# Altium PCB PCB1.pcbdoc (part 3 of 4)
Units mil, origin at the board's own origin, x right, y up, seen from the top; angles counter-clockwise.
Board outline 4701.34 x 4268.46 mil, 2 copper layers (Top Layer, Bottom Layer); 341 components, 58 nets, 1384 pads, 312 vias.
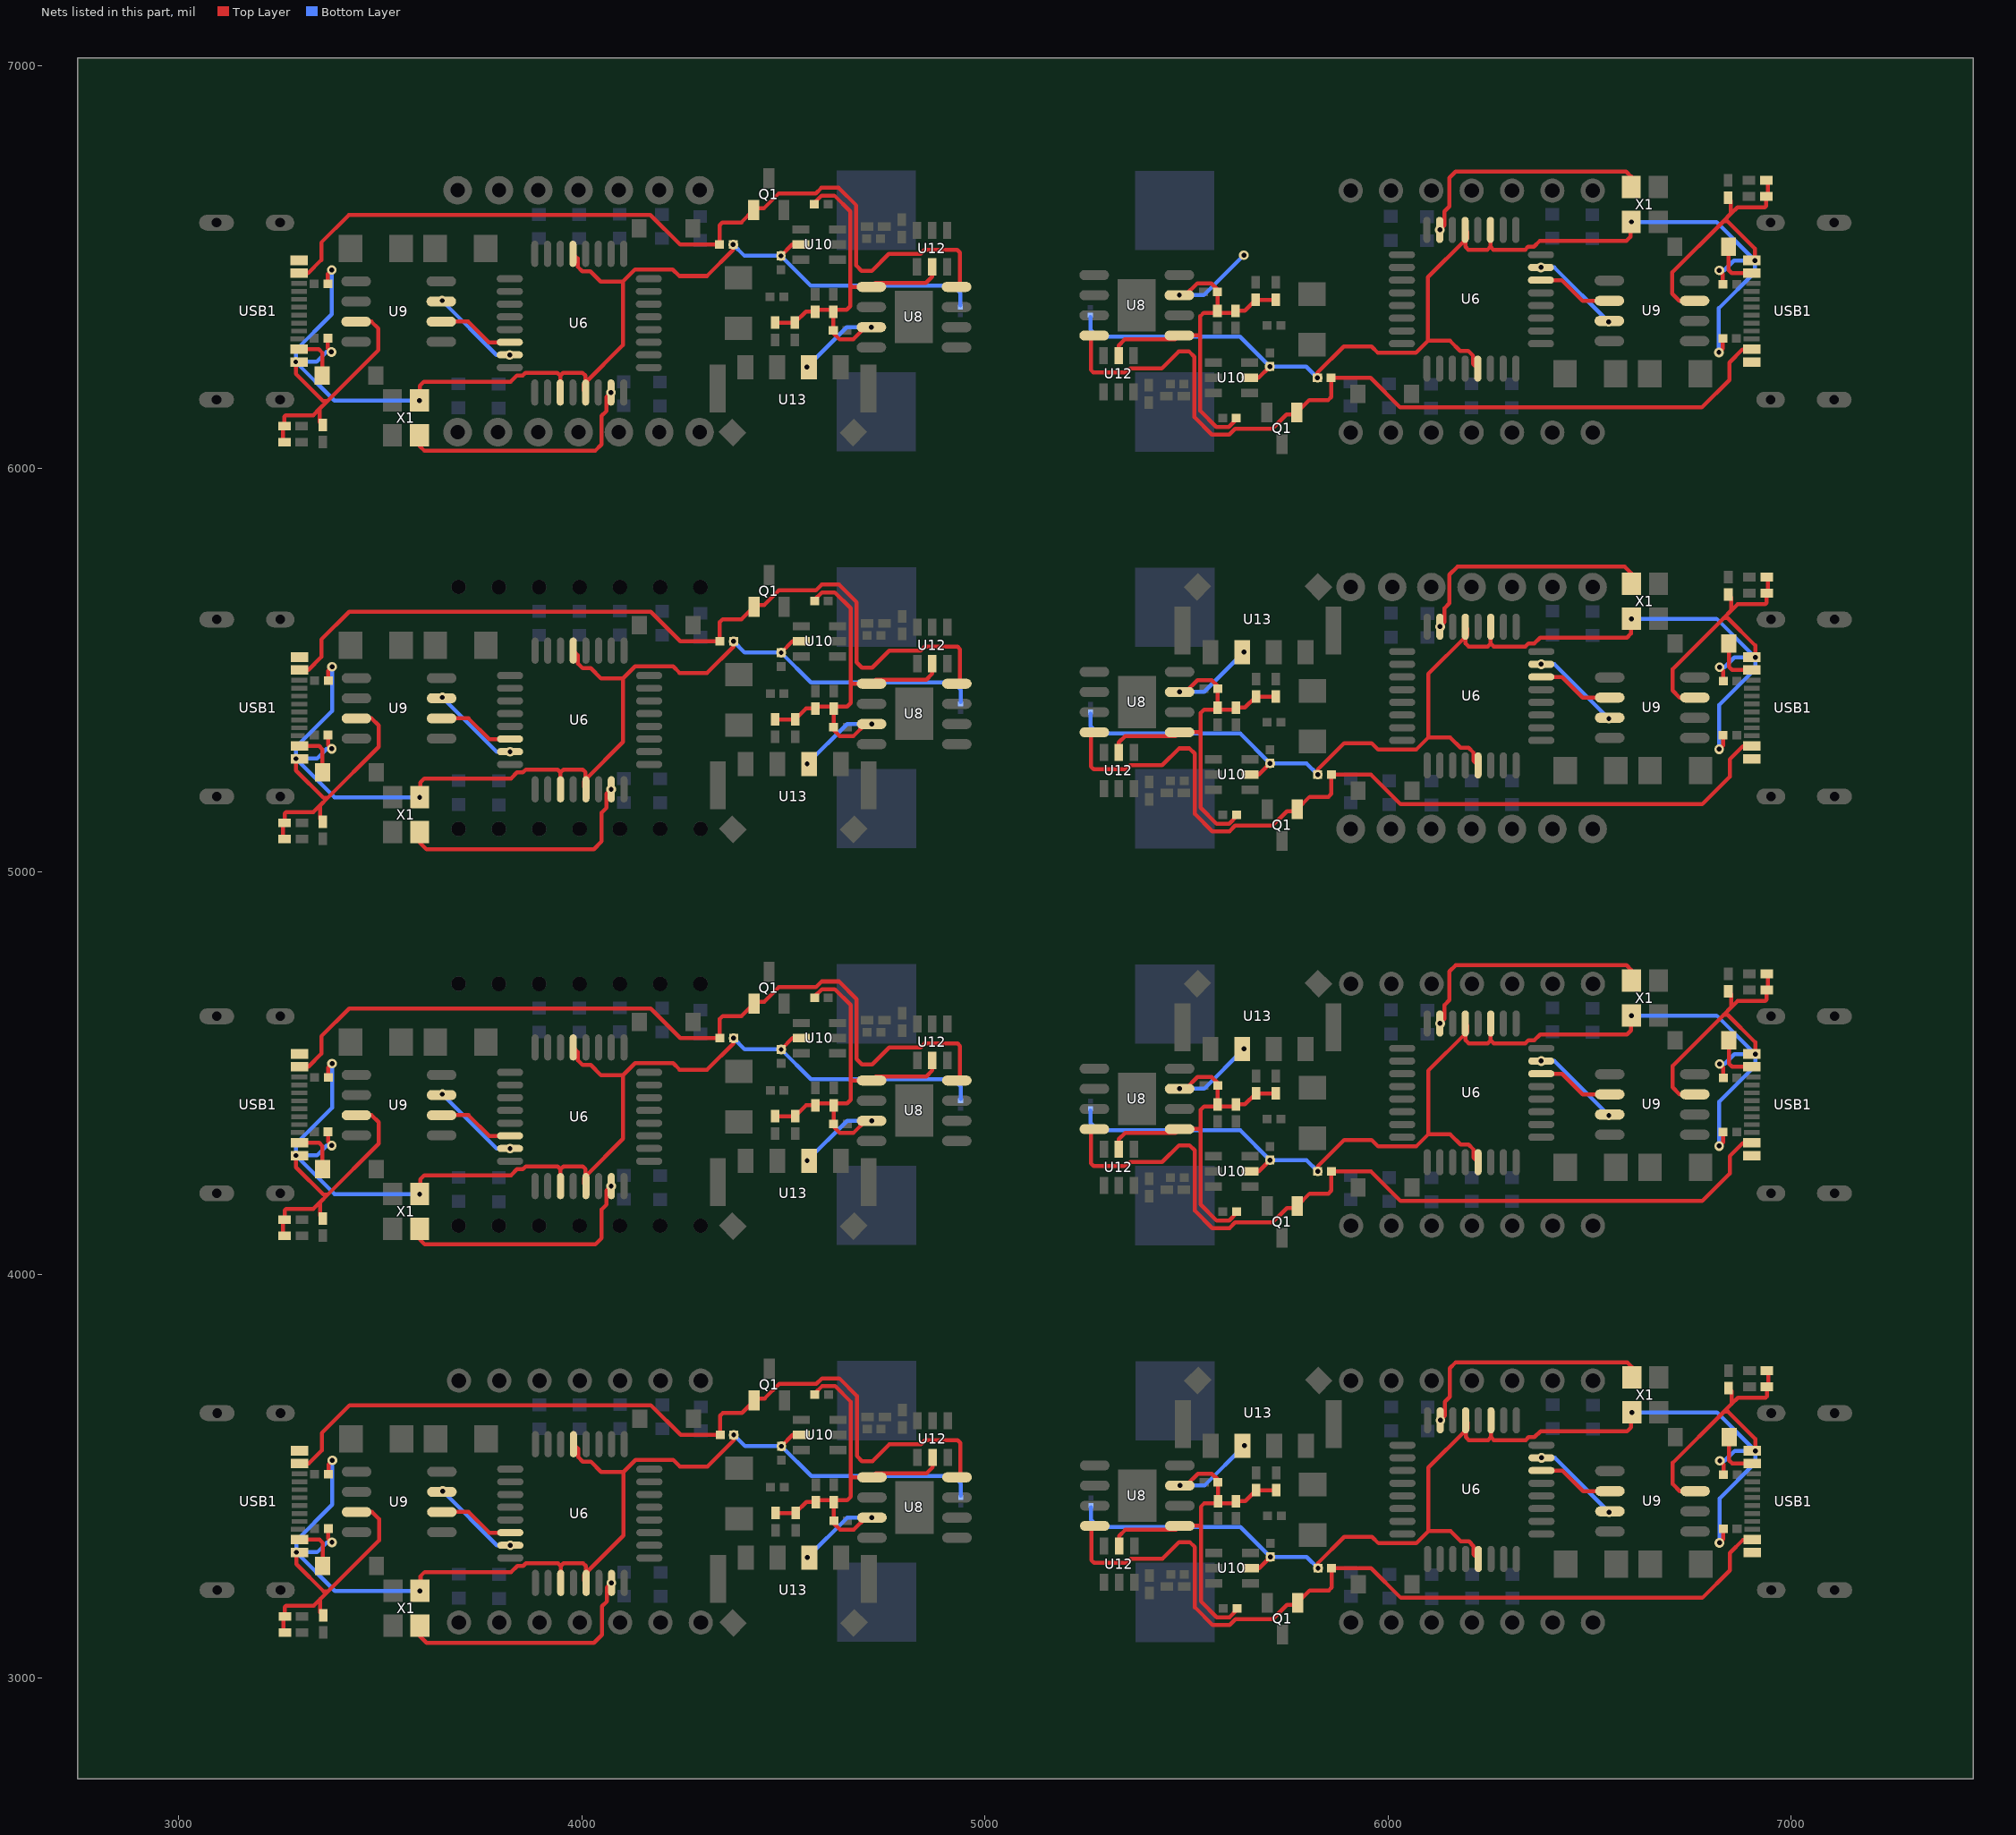
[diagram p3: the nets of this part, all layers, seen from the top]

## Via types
v1: diameter 24.02, hole 12.01, Top Layer to Bottom Layer, 312 vias

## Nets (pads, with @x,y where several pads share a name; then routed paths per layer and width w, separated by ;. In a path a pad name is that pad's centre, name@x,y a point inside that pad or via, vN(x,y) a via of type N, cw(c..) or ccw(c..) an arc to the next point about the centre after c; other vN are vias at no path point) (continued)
POWER_GND: C15.2 C16.2 C19.1 C20.1 C21.2 C25.1 C27.1 R22.2 R48.2 R49.2 R50.2 R51.1 R52.1 R54.1 U6.3 U6.5 U6.21 U8.1 U8.3 U9.3 U10.2 U12.2 U13.2 USB1.A1B12 USB1.B1A12 X1.2 | length 37515.7
  Top Layer w10: C21.2@3262.65,6065.59 3259.11,6069.13 3259.11,6102.05 C25.1@3262.65,6105.59 3262.65,6129.1 3266.01,6132.46 3334.38,6132.46 3350.46,6148.55 ; C21.2@3263.32,4097.09 3259.78,4100.63 3259.78,4133.55 C25.1@3263.32,4137.09 3263.32,4160.6 3266.68,4163.96 3335.04,4163.96 3351.13,4180.05 ; C21.2@3263.32,5081.34 3259.78,5084.88 3259.78,5117.8 C25.1@3263.32,5121.34 3263.32,5144.85 3266.68,5148.21 3335.04,5148.21 3351.13,5164.3 ; C21.2@3263.99,3112.83 3260.45,3116.37 3260.45,3149.29 C25.1@3263.99,3152.83 3263.99,3176.35 3267.35,3179.71 3335.71,3179.71 3351.8,3195.79 ; v1(3290.88,6264.61) 3290.88,6235.32 3359.26,6166.94 3368.85,6166.94 ; v1(3291.55,4296.11) 3291.55,4266.81 3359.93,4198.43 3369.52,4198.43 ; v1(3291.55,5280.36) 3291.55,5251.06 3359.93,5182.68 3369.52,5182.68 ; v1(3292.22,3311.85) 3292.22,3282.56 3360.6,3214.18 3370.19,3214.18 ; C27.1@3357.65,6108.51 3350.46,6115.7 3350.46,6148.55 ; C27.1@3358.32,4140.01 3351.13,4147.19 3351.13,4180.05 ; C27.1@3358.32,5124.26 3351.13,5131.45 3351.13,5164.3 ; C27.1@3358.99,3155.75 3351.8,3162.94 3351.8,3195.79 ; R52.1@3370.31,6323.41 3370.31,6298.35 v1(3379.41,6289.25) ; R51.1@3370.71,6458.2 3370.71,6483.1 v1(3380.26,6492.65) ; R52.1@3370.98,4354.9 3370.98,4329.85 v1(3380.08,4320.75) ; R52.1@3370.98,5339.16 3370.98,5314.1 v1(3380.08,5305) ; R51.1@3371.38,4489.69 3371.38,4514.59 v1(3380.93,4524.14) ; R51.1@3371.38,5473.94 3371.38,5498.85 v1(3380.93,5508.39) ; R52.1@3371.64,3370.65 3371.64,3345.6 v1(3380.75,3336.49) ; R51.1@3372.05,3505.44 3372.05,3530.34 v1(3381.59,3539.89) ; U9.3@3440.67,6364.53 3478.49,6364.53 3495.98,6347.03 3495.98,6294.07 3368.85,6166.94 ; U9.3@3441.33,4396.02 3479.15,4396.02 3496.65,4378.52 3496.65,4325.57 3369.52,4198.43 ; U9.3@3441.33,5380.28 3479.15,5380.28 3496.65,5362.78 3496.65,5309.82 3369.52,5182.68 ; U9.3@3442,3411.77 3479.82,3411.77 3497.32,3394.27 3497.32,3341.31 3370.19,3214.18 ; X1.2@3599.11,6170.44 3599.11,6205.59 3609.11,6215.59 3824.11,6215.59 3839.03,6230.51 3853.45,6230.51 3860.6,6237.66 3939.8,6237.66 3946.87,6230.59 ; X1.2@3599.78,4201.93 3599.78,4237.09 3609.78,4247.09 3824.78,4247.09 3839.7,4262.01 3854.12,4262.01 3861.27,4269.16 3940.46,4269.16 3947.53,4262.09 ; X1.2@3599.78,5186.18 3599.78,5221.34 3609.78,5231.34 3824.78,5231.34 3839.7,5246.26 3854.12,5246.26 3861.27,5253.41 3940.46,5253.41 3947.53,5246.34 ; X1.2@3600.45,3217.68 3600.45,3252.83 3610.45,3262.83 3825.45,3262.83 3840.37,3277.75 3854.79,3277.75 3861.94,3284.9 3941.13,3284.9 3948.2,3277.83 ; U6.3@3946.87,6188.59 3946.87,6230.59 ; U6.3@3947.53,4220.09 3947.53,4262.09 ; U6.3@3947.53,5204.34 3947.53,5246.34 ; U6.3@3948.2,3235.83 3948.2,3277.83 ; U6.21@3978.36,6532.59 3990.02,6520.94 3990.02,6500.75 4001.64,6489.13 4021.83,6489.13 4047.12,6463.83 4102.1,6463.83 ; U6.21@3979.03,4564.09 3990.68,4552.43 3990.68,4532.24 4002.31,4520.62 4022.5,4520.62 4047.79,4495.33 4102.77,4495.33 ; U6.21@3979.03,5548.34 3990.68,5536.69 3990.68,5516.5 4002.31,5504.87 4022.5,5504.87 4047.79,5479.58 4102.77,5479.58 ; U6.21@3979.7,3579.83 3991.35,3568.18 3991.35,3547.99 4002.98,3536.37 4023.16,3536.37 4048.45,3511.08 4103.44,3511.08 ; U6.5@4009.86,6188.59 U6.5@4009.11,6189.34 ; U6.5@4010.53,4220.09 U6.5@4009.78,4220.83 ; U6.5@4010.53,5204.34 U6.5@4009.78,5205.09 ; U6.5@4011.19,3235.83 U6.5@4010.45,3236.58 ; v1(4375.86,6555.59) 4375.86,6542.85 4310.61,6477.6 4242.1,6477.6 4225.88,6493.82 4132.09,6493.82 4102.1,6463.83 ; v1(4376.52,4587.09) 4376.52,4574.34 4311.27,4509.09 4242.77,4509.09 4226.55,4525.31 4132.75,4525.31 4102.77,4495.33 ; v1(4376.52,5571.34) 4376.52,5558.6 4311.27,5493.35 4242.77,5493.35 4226.55,5509.57 4132.75,5509.57 4102.77,5479.58 ; v1(4377.19,3602.83) 4377.19,3590.09 4311.94,3524.84 4243.44,3524.84 4227.22,3541.06 4133.42,3541.06 4103.44,3511.08 ; C19.1@4479.57,6362.05 C20.1@4529.11,6362.05 4556.19,6389.13 C15.2@4579.11,6389.13 4584.11,6394.13 C16.2@4627.65,6394.13 ; C19.1@4480.24,4393.55 C20.1@4529.78,4393.55 4556.86,4420.63 C15.2@4579.78,4420.63 4584.78,4425.63 C16.2@4628.32,4425.63 ; C19.1@4480.24,5377.8 C20.1@4529.78,5377.8 4556.86,5404.88 C15.2@4579.78,5404.88 4584.78,5409.88 C16.2@4628.32,5409.88 ; C19.1@4480.91,3409.29 C20.1@4530.45,3409.29 4557.53,3436.37 C15.2@4580.45,3436.37 4585.45,3441.37 C16.2@4628.99,3441.37 ; v1(4494.11,6527.63) 4522.07,6555.59 U10.2@4543.87,6555.59 ; v1(4494.78,4559.13) 4522.73,4587.08 U10.2@4544.54,4587.08 ; v1(4494.78,5543.38) 4522.73,5571.33 U10.2@4544.54,5571.33 ; v1(4495.45,3574.87) 4523.4,3602.83 U10.2@4545.21,3602.83 ; R50.2@4577.07,6655.59 4577.07,6658.81 4595.47,6677.2 4626.83,6677.2 4666.44,6637.6 4666.44,6455.07 ; R50.2@4577.74,4687.09 4577.74,4690.31 4596.13,4708.7 4627.5,4708.7 4667.11,4669.1 4667.11,4486.57 ; R50.2@4577.74,5671.34 4577.74,5674.56 4596.13,5692.95 4627.5,5692.95 4667.11,5653.35 4667.11,5470.82 ; R50.2@4578.41,3702.83 4578.41,3706.05 4596.8,3724.45 4628.17,3724.45 4667.78,3684.84 4667.78,3502.31 ; v1(4718.5,6350.59) 4703.45,6350.59 4673.88,6321.02 4639.11,6321.02 4624.11,6336.02 4624.11,6390.59 C16.2@4627.65,6394.13 ; v1(4719.17,4382.09) 4704.12,4382.09 4674.54,4352.51 4639.78,4352.51 4624.78,4367.51 4624.78,4422.09 C16.2@4628.32,4425.63 ; v1(4719.17,5366.34) 4704.12,5366.34 4674.54,5336.76 4639.78,5336.76 4624.78,5351.76 4624.78,5406.34 C16.2@4628.32,5409.88 ; v1(4719.84,3397.83) 4704.79,3397.83 4675.21,3368.26 4640.45,3368.26 4625.45,3383.26 4625.45,3437.83 C16.2@4628.99,3441.37 ; U12.2@4864.11,6495.59 U12.2@4868.99,6500.47 ; U12.2@4864.78,4527.09 U12.2@4869.66,4531.97 ; U12.2@4864.78,5511.34 U12.2@4869.66,5516.22 ; U12.2@4865.45,3542.83 U12.2@4870.33,3547.71 ; U12.2@4869.11,6500.35 4869.11,6475.59 4854.11,6460.59 4728.5,6460.59 U8.1@4718.5,6450.59 4670.92,6450.59 4666.44,6455.07 ; U12.2@4869.78,4531.85 4869.78,4507.09 4854.78,4492.09 4729.17,4492.09 U8.1@4719.17,4482.09 4671.59,4482.09 4667.11,4486.57 ; U12.2@4869.78,5516.1 4869.78,5491.34 4854.78,5476.34 4729.17,5476.34 U8.1@4719.17,5466.34 4671.59,5466.34 4667.11,5470.82 ; U12.2@4870.45,3547.59 4870.45,3522.83 4855.45,3507.83 4729.84,3507.83 U8.1@4719.84,3497.83 4672.26,3497.83 4667.78,3502.31 ; U12.2@5331.72,6280.32 5331.72,6305.08 5346.72,6320.08 5472.33,6320.08 U8.1@5482.33,6330.08 5529.91,6330.08 5534.39,6325.6 ; U12.2@5331.84,6280.2 U12.2@5336.72,6285.08 ; U12.2@5332.38,4311.82 5332.38,4336.58 5347.38,4351.58 5472.99,4351.58 U8.1@5482.99,4361.58 5530.57,4361.58 5535.05,4357.1 ; U12.2@5332.38,5296.07 5332.38,5320.83 5347.38,5335.83 5472.99,5335.83 U8.1@5482.99,5345.83 5530.57,5345.83 5535.05,5341.35 ; U12.2@5332.5,4311.7 U12.2@5337.38,4316.58 ; U12.2@5332.5,5295.95 U12.2@5337.38,5300.83 ; U12.2@5333.05,3327.57 5333.05,3352.33 5348.05,3367.33 5473.66,3367.33 U8.1@5483.66,3377.33 5531.24,3377.33 5535.72,3372.85 ; U12.2@5333.17,3327.45 U12.2@5338.05,3332.33 ; v1(5482.33,6430.08) 5497.38,6430.08 5526.95,6459.66 5561.72,6459.66 5576.72,6444.66 5576.72,6390.08 C16.2@5573.18,6386.54 ; v1(5482.99,4461.58) 5498.04,4461.58 5527.62,4491.15 5562.38,4491.15 5577.38,4476.15 5577.38,4421.58 C16.2@5573.84,4418.04 ; v1(5482.99,5445.83) 5498.04,5445.83 5527.62,5475.4 5562.38,5475.4 5577.38,5460.4 5577.38,5405.83 C16.2@5573.84,5402.29 ; v1(5483.66,3477.33) 5498.71,3477.33 5528.29,3506.9 5563.05,3506.9 5578.05,3491.9 5578.05,3437.33 C16.2@5574.51,3433.79 ; R50.2@5623.76,6125.08 5623.76,6121.86 5605.36,6103.47 5573.99,6103.47 5534.39,6143.07 5534.39,6325.6 ; R50.2@5624.42,4156.58 5624.42,4153.36 5606.03,4134.96 5574.66,4134.96 5535.05,4174.57 5535.05,4357.1 ; R50.2@5624.42,5140.83 5624.42,5137.61 5606.03,5119.22 5574.66,5119.22 5535.05,5158.82 5535.05,5341.35 ; R50.2@5625.09,3172.33 5625.09,3169.11 5606.7,3150.71 5575.33,3150.71 5535.72,3190.31 5535.72,3372.85 ; U10.2@5656.95,6225.09 5678.76,6225.09 v1(5706.72,6253.04) ; U10.2@5657.62,4256.58 5679.43,4256.58 v1(5707.38,4284.54) ; U10.2@5657.62,5240.83 5679.43,5240.83 v1(5707.38,5268.79) ; U10.2@5658.29,3272.33 5680.1,3272.33 v1(5708.05,3300.29) ; C19.1@5721.26,6418.62 C20.1@5671.72,6418.62 5644.64,6391.54 C15.2@5621.72,6391.54 5616.72,6386.54 C16.2@5573.18,6386.54 ; C19.1@5721.92,4450.12 C20.1@5672.38,4450.12 5645.3,4423.04 C15.2@5622.38,4423.04 5617.38,4418.04 C16.2@5573.84,4418.04 ; C19.1@5721.92,5434.37 C20.1@5672.38,5434.37 5645.3,5407.29 C15.2@5622.38,5407.29 5617.38,5402.29 C16.2@5573.84,5402.29 ; C19.1@5722.59,3465.87 C20.1@5673.05,3465.87 5645.97,3438.79 C15.2@5623.05,3438.79 5618.05,3433.79 C16.2@5574.51,3433.79 ; v1(5824.97,6225.08) 5824.97,6237.83 5890.22,6303.07 5958.72,6303.07 5974.94,6286.85 6068.74,6286.85 6098.72,6316.84 ; v1(5825.64,4256.58) 5825.64,4269.32 5890.89,4334.57 5959.39,4334.57 5975.61,4318.35 6069.41,4318.35 6099.39,4348.33 ; v1(5825.64,5240.83) 5825.64,5253.57 5890.89,5318.82 5959.39,5318.82 5975.61,5302.6 6069.41,5302.6 6099.39,5332.59 ; v1(5826.31,3272.33) 5826.31,3285.07 5891.56,3350.32 5960.06,3350.32 5976.28,3334.1 6070.08,3334.1 6100.06,3364.08 ; U6.5@6190.97,6592.08 U6.5@6191.72,6591.33 ; U6.5@6191.64,4623.58 U6.5@6192.38,4622.83 ; U6.5@6191.64,5607.83 U6.5@6192.38,5607.08 ; U6.5@6192.3,3639.33 U6.5@6193.05,3638.58 ; U6.21@6222.46,6248.08 6210.81,6259.74 6210.81,6279.92 6199.19,6291.55 6179,6291.55 6153.71,6316.84 6098.72,6316.84 ; U6.21@6223.13,4279.58 6211.48,4291.23 6211.48,4311.42 6199.85,4323.04 6179.67,4323.04 6154.38,4348.33 6099.39,4348.33 ; U6.21@6223.13,5263.83 6211.48,5275.48 6211.48,5295.67 6199.85,5307.29 6179.67,5307.29 6154.38,5332.59 6099.39,5332.59 ; U6.21@6223.8,3295.33 6212.15,3306.98 6212.15,3327.17 6200.52,3338.79 6180.34,3338.79 6155.04,3364.08 6100.06,3364.08 ; U6.3@6253.96,6592.08 6253.96,6550.08 ; U6.3@6254.63,4623.58 6254.63,4581.58 ; U6.3@6254.63,5607.83 6254.63,5565.83 ; U6.3@6255.3,3639.33 6255.3,3597.33 ; X1.2@6601.72,6610.24 6601.72,6575.08 6591.72,6565.08 6376.72,6565.08 6361.79,6550.16 6347.37,6550.16 6340.22,6543.01 6261.03,6543.01 6253.96,6550.08 ; X1.2@6602.38,4641.73 6602.38,4606.58 6592.38,4596.58 6377.38,4596.58 6362.46,4581.66 6348.04,4581.66 6340.89,4574.51 6261.7,4574.51 6254.63,4581.58 ; X1.2@6602.38,5625.98 6602.38,5590.83 6592.38,5580.83 6377.38,5580.83 6362.46,5565.91 6348.04,5565.91 6340.89,5558.76 6261.7,5558.76 6254.63,5565.83 ; X1.2@6603.05,3657.48 6603.05,3622.33 6593.05,3612.33 6378.05,3612.33 6363.13,3597.4 6348.71,3597.4 6341.56,3590.25 6262.37,3590.25 6255.3,3597.33 ; U9.3@6760.16,6416.15 6722.34,6416.15 6704.84,6433.64 6704.84,6486.6 6831.98,6613.74 ; U9.3@6760.83,4447.64 6723.01,4447.64 6705.51,4465.14 6705.51,4518.1 6832.64,4645.23 ; U9.3@6760.83,5431.89 6723.01,5431.89 6705.51,5449.39 6705.51,5502.35 6832.64,5629.48 ; U9.3@6761.5,3463.39 6723.68,3463.39 6706.18,3480.89 6706.18,3533.84 6833.31,3660.98 ; v1(6820.57,6288.03) 6830.12,6297.57 R51.1@6830.12,6322.48 ; v1(6821.24,4319.52) 6830.78,4329.07 R51.1@6830.78,4353.97 ; v1(6821.24,5303.78) 6830.78,5313.32 R51.1@6830.78,5338.22 ; v1(6821.42,6491.42) 6830.52,6482.32 R52.1@6830.52,6457.27 ; v1(6821.91,3335.27) 6831.45,3344.82 R51.1@6831.45,3369.72 ; v1(6822.08,4522.92) 6831.19,4513.82 R52.1@6831.19,4488.76 ; v1(6822.08,5507.17) 6831.19,5498.07 R52.1@6831.19,5473.01 ; v1(6822.75,3538.67) 6831.86,3529.56 R52.1@6831.86,3504.51 ; C27.1@6843.18,6672.16 6850.36,6664.98 6850.36,6632.12 ; C27.1@6843.84,4703.66 6851.03,4696.47 6851.03,4663.62 ; C27.1@6843.84,5687.91 6851.03,5680.72 6851.03,5647.87 ; C27.1@6844.51,3719.41 6851.7,3712.22 6851.7,3679.37 ; v1(6909.94,6516.06) 6909.94,6545.36 6841.56,6613.74 6831.98,6613.74 ; v1(6910.61,4547.56) 6910.61,4576.85 6842.23,4645.23 6832.64,4645.23 ; v1(6910.61,5531.81) 6910.61,5561.1 6842.23,5629.48 6832.64,5629.48 ; v1(6911.28,3563.3) 6911.28,3592.6 6842.9,3660.98 6833.31,3660.98 ; C21.2@6938.18,6715.08 6941.72,6711.54 6941.72,6678.62 C25.1@6938.18,6675.08 6938.18,6651.57 6934.81,6648.21 6866.45,6648.21 6850.36,6632.12 ; C21.2@6938.84,4746.58 6942.38,4743.04 6942.38,4710.12 C25.1@6938.84,4706.58 6938.84,4683.07 6935.48,4679.71 6867.12,4679.71 6851.03,4663.62 ; C21.2@6938.84,5730.83 6942.38,5727.29 6942.38,5694.37 C25.1@6938.84,5690.83 6938.84,5667.32 6935.48,5663.96 6867.12,5663.96 6851.03,5647.87 ; C21.2@6939.51,3762.33 6943.05,3758.79 6943.05,3725.87 C25.1@6939.51,3722.33 6939.51,3698.81 6936.15,3695.45 6867.79,3695.45 6851.7,3679.37 ; 3350.46,6148.55 3368.85,6166.94 ; 3351.13,4180.05 3369.52,4198.43 ; 3351.13,5164.3 3369.52,5182.68 ; 3351.8,3195.79 3370.19,3214.18 ; 3946.87,6230.59 3953.94,6237.66 4002.04,6237.66 4009.11,6230.59 U6.5@4009.11,6213.03 ; 3947.53,4262.09 3954.61,4269.16 4002.71,4269.16 4009.78,4262.09 U6.5@4009.78,4244.53 ; 3947.53,5246.34 3954.61,5253.41 4002.71,5253.41 4009.78,5246.34 U6.5@4009.78,5228.78 ; 3948.2,3277.83 3955.27,3284.9 4003.38,3284.9 4010.45,3277.83 U6.5@4010.45,3260.27 ; U6.5@4009.11,6189.34 4004.86,6193.59 4004.86,6208.78 U6.5@4009.11,6213.03 ; U6.5@4009.11,6189.34 U6.5@4009.11,6213.03 ; U6.5@4009.11,6213.03 4102.1,6306.02 4102.1,6463.83 ; U6.5@4009.78,4220.83 U6.5@4009.78,4244.53 ; U6.5@4009.78,4220.83 4005.53,4225.09 4005.53,4240.27 U6.5@4009.78,4244.53 ; U6.5@4009.78,4244.53 4102.77,4337.52 4102.77,4495.33 ; U6.5@4009.78,5205.09 U6.5@4009.78,5228.78 ; U6.5@4009.78,5205.09 4005.53,5209.34 4005.53,5224.53 U6.5@4009.78,5228.78 ; U6.5@4009.78,5228.78 4102.77,5321.77 4102.77,5479.58 ; U6.5@4010.45,3236.58 4006.19,3240.83 4006.19,3256.02 U6.5@4010.45,3260.27 ; U6.5@4010.45,3236.58 U6.5@4010.45,3260.27 ; U6.5@4010.45,3260.27 4103.44,3353.27 4103.44,3511.08 ; C16.2@4627.65,6394.13 4657.65,6394.13 4666.44,6402.92 4666.44,6455.07 ; C16.2@4628.32,4425.63 4658.32,4425.63 4667.11,4434.41 4667.11,4486.57 ; C16.2@4628.32,5409.88 4658.32,5409.88 4667.11,5418.67 4667.11,5470.82 ; C16.2@4628.99,3441.37 4658.99,3441.37 4667.78,3450.16 4667.78,3502.31 ; 5534.39,6325.6 5534.39,6377.75 5543.18,6386.54 C16.2@5573.18,6386.54 ; 5535.05,4357.1 5535.05,4409.25 5543.84,4418.04 C16.2@5573.84,4418.04 ; 5535.05,5341.35 5535.05,5393.5 5543.84,5402.29 C16.2@5573.84,5402.29 ; 5535.72,3372.85 5535.72,3425 5544.51,3433.79 C16.2@5574.51,3433.79 ; 6098.72,6316.84 6098.72,6474.65 U6.5@6191.72,6567.64 ; 6099.39,4348.33 6099.39,4506.15 U6.5@6192.38,4599.14 ; 6099.39,5332.59 6099.39,5490.4 U6.5@6192.38,5583.39 ; 6100.06,3364.08 6100.06,3521.89 U6.5@6193.05,3614.89 ; U6.5@6191.72,6567.64 U6.5@6191.72,6591.33 ; U6.5@6191.72,6567.64 6191.72,6550.08 6198.79,6543.01 6246.89,6543.01 6253.96,6550.08 ; U6.5@6191.72,6567.64 6195.97,6571.89 6195.97,6587.08 U6.5@6191.72,6591.33 ; U6.5@6192.38,4599.14 U6.5@6192.38,4622.83 ; U6.5@6192.38,4599.14 6192.38,4581.58 6199.45,4574.51 6247.56,4574.51 6254.63,4581.58 ; U6.5@6192.38,4599.14 6196.64,4603.39 6196.64,4618.58 U6.5@6192.38,4622.83 ; U6.5@6192.38,5583.39 U6.5@6192.38,5607.08 ; U6.5@6192.38,5583.39 6192.38,5565.83 6199.45,5558.76 6247.56,5558.76 6254.63,5565.83 ; U6.5@6192.38,5583.39 6196.64,5587.64 6196.64,5602.83 U6.5@6192.38,5607.08 ; U6.5@6193.05,3614.89 U6.5@6193.05,3638.58 ; U6.5@6193.05,3614.89 6193.05,3597.33 6200.12,3590.25 6248.23,3590.25 6255.3,3597.33 ; U6.5@6193.05,3614.89 6197.3,3619.14 6197.3,3634.33 U6.5@6193.05,3638.58 ; 6831.98,6613.74 6850.36,6632.12 ; 6832.64,4645.23 6851.03,4663.62 ; 6832.64,5629.48 6851.03,5647.87 ; 6833.31,3660.98 6851.7,3679.37
  Bottom Layer w10: v1(3379.41,6289.25) 3367.34,6289.25 3342.7,6264.61 v1(3290.88,6264.61) ; v1(3380.08,4320.75) 3368.01,4320.75 3343.37,4296.11 v1(3291.55,4296.11) ; v1(3380.08,5305) 3368.01,5305 3343.37,5280.36 v1(3291.55,5280.36) ; v1(3380.26,6492.65) 3380.26,6382.88 3290.88,6293.5 v1(3290.88,6264.61) ; v1(3380.75,3336.49) 3368.67,3336.49 3344.04,3311.85 v1(3292.22,3311.85) ; v1(3380.93,4524.14) 3380.93,4414.37 3291.55,4325 v1(3291.55,4296.11) ; v1(3380.93,5508.39) 3380.93,5398.63 3291.55,5309.25 v1(3291.55,5280.36) ; v1(3381.59,3539.89) 3381.59,3430.12 3292.22,3340.75 v1(3292.22,3311.85) ; v1(3597.58,6168.9) 3386.59,6168.9 v1(3290.88,6264.61) ; v1(3598.24,4200.4) 3387.26,4200.4 v1(3291.55,4296.11) ; v1(3598.24,5184.65) 3387.26,5184.65 v1(3291.55,5280.36) ; v1(3598.91,3216.14) 3387.93,3216.14 v1(3292.22,3311.85) ; v1(4375.86,6555.59) 4403.82,6527.63 v1(4494.11,6527.63) 4568.13,6453.62 4920.83,6453.62 4939.11,6435.34 R22.2@4939.11,6404.47 ; v1(4376.52,4587.09) 4404.48,4559.13 v1(4494.78,4559.13) 4568.79,4485.11 4921.5,4485.11 4939.78,4466.83 R22.2@4939.78,4435.97 ; v1(4376.52,5571.34) 4404.48,5543.38 v1(4494.78,5543.38) 4568.79,5469.36 4921.5,5469.36 4939.78,5451.09 R22.2@4939.78,5420.22 ; v1(4377.19,3602.83) 4405.15,3574.87 v1(4495.45,3574.87) 4569.46,3500.86 4922.17,3500.86 4940.45,3482.58 R22.2@4940.45,3451.72 ; v1(4558.48,6251.56) 4657.52,6350.59 v1@4714.11,6350.59 ; v1(4559.15,4283.05) 4658.18,4382.09 v1@4714.78,4382.09 ; v1(4559.15,5267.3) 4658.18,5366.34 v1@4714.78,5366.34 ; v1(4559.82,3298.8) 4658.85,3397.83 v1@4715.45,3397.83 ; R22.2@5261.72,6376.2 5261.72,6345.34 5279.99,6327.06 5632.7,6327.06 v1(5706.72,6253.04) 5797.01,6253.04 v1(5824.97,6225.08) ; R22.2@5262.38,4407.7 5262.38,4376.83 5280.66,4358.55 5633.37,4358.55 v1(5707.38,4284.54) 5797.68,4284.54 v1(5825.64,4256.58) ; R22.2@5262.38,5391.95 5262.38,5361.08 5280.66,5342.81 5633.37,5342.81 v1(5707.38,5268.79) 5797.68,5268.79 v1(5825.64,5240.83) ; R22.2@5263.05,3423.44 5263.05,3392.58 5281.33,3374.3 5634.04,3374.3 v1(5708.05,3300.29) 5798.35,3300.29 v1(5826.31,3272.33) ; v1@5486.72,6430.08 5543.31,6430.08 v1(5642.34,6529.12) ; v1@5487.38,4461.58 5543.98,4461.58 v1(5643.01,4560.61) ; v1@5487.38,5445.83 5543.98,5445.83 v1(5643.01,5544.86) ; v1@5488.05,3477.33 5544.65,3477.33 v1(5643.68,3576.36) ; v1(6603.25,6611.77) 6814.23,6611.77 v1(6909.94,6516.06) ; v1(6603.92,4643.27) 6814.9,4643.27 v1(6910.61,4547.56) ; v1(6603.92,5627.52) 6814.9,5627.52 v1(6910.61,5531.81) ; v1(6604.59,3659.02) 6815.57,3659.02 v1(6911.28,3563.3) ; v1(6820.57,6288.03) 6820.57,6397.8 6909.94,6487.17 v1(6909.94,6516.06) ; v1(6821.24,4319.52) 6821.24,4429.29 6910.61,4518.67 v1(6910.61,4547.56) ; v1(6821.24,5303.78) 6821.24,5413.54 6910.61,5502.92 v1(6910.61,5531.81) ; v1(6821.42,6491.42) 6833.49,6491.42 6858.13,6516.06 v1(6909.94,6516.06) ; v1(6821.91,3335.27) 6821.91,3445.04 6911.28,3534.41 v1(6911.28,3563.3) ; v1(6822.08,4522.92) 6834.16,4522.92 6858.79,4547.56 v1(6910.61,4547.56) ; v1(6822.08,5507.17) 6834.16,5507.17 6858.79,5531.81 v1(6910.61,5531.81) ; v1(6822.75,3538.67) 6834.82,3538.67 6859.46,3563.3 v1(6911.28,3563.3)
POWER_VBUS: D6.2 Q1.1 R54.2 U8.8 USB1.A4B9 USB1.B4A9 | length 17960.8
  Top Layer w10: USB1.B4A9@3295.2,6295.85 3348.35,6295.85 3356.42,6287.78 D6.2@3356.42,6230.59 ; USB1.B4A9@3295.87,4327.34 3349.02,4327.34 3357.09,4319.27 D6.2@3357.09,4262.09 ; USB1.B4A9@3295.87,5311.59 3349.02,5311.59 3357.09,5303.52 D6.2@3357.09,5246.34 ; USB1.B4A9@3296.53,3343.09 3349.68,3343.09 3357.75,3335.02 D6.2@3357.75,3277.83 ; USB1.A4B9@3302.09,6484.83 3302.34,6485.08 3321.82,6485.08 3354.25,6517.51 3354.25,6560.73 3422.73,6629.21 4170.49,6629.21 4244.11,6555.59 R54.2@4342.07,6555.59 4342.04,6603.52 4349.11,6610.59 4396.08,6610.59 Q1.1@4426.71,6641.22 4431.71,6646.22 4452.59,6646.22 4488.18,6681.81 4565.99,6681.81 4566.39,6682.2 4580.64,6682.2 4594.66,6696.22 4637.64,6696.22 4681.11,6652.75 4681.11,6503.59 4694.11,6490.59 4720.01,6490.59 4761.85,6532.44 4840.25,6532.44 4850.25,6542.44 4931.53,6542.44 4937.97,6536 4937.97,6458.84 U8.8@4929.72,6450.59 ; USB1.A4B9@3302.76,4516.32 3303.01,4516.58 3322.49,4516.58 3354.92,4549.01 3354.92,4592.23 3423.4,4660.71 4171.16,4660.71 4244.78,4587.09 R54.2@4342.74,4587.09 ; USB1.A4B9@3302.76,5500.57 3303.01,5500.83 3322.49,5500.83 3354.92,5533.26 3354.92,5576.48 3423.4,5644.96 4171.16,5644.96 4244.78,5571.34 R54.2@4342.74,5571.34 ; USB1.A4B9@3303.42,3532.07 3303.68,3532.32 3323.16,3532.32 3355.59,3564.76 3355.59,3607.97 3424.07,3676.46 4171.82,3676.46 4245.45,3602.83 R54.2@4343.41,3602.83 4343.38,3650.76 4350.45,3657.83 4397.42,3657.83 Q1.1@4428.05,3688.46 4433.05,3693.46 4453.93,3693.46 4489.52,3729.05 4567.33,3729.05 4567.72,3729.45 4581.98,3729.45 4596,3743.46 4638.98,3743.46 4682.45,3699.99 4682.45,3550.83 4695.45,3537.83 4721.34,3537.83 4763.19,3579.68 4841.58,3579.68 4851.58,3589.68 4932.87,3589.68 4939.3,3583.25 4939.3,3506.08 U8.8@4931.06,3497.83 ; R54.2@4342.74,4587.09 4342.71,4635.01 4349.78,4642.09 4396.75,4642.09 Q1.1@4427.38,4672.72 4432.38,4677.72 4453.26,4677.72 4488.85,4713.31 4566.66,4713.31 4567.05,4713.7 4581.31,4713.7 4595.33,4727.72 4638.31,4727.72 4681.78,4684.24 4681.78,4535.08 4694.78,4522.09 4720.68,4522.09 4762.52,4563.93 4840.92,4563.93 4850.92,4573.93 4932.2,4573.93 4938.64,4567.5 4938.64,4490.33 U8.8@4930.39,4482.09 ; R54.2@4342.71,5571.37 4342.71,5619.27 4349.78,5626.34 4396.75,5626.34 Q1.1@4427.38,5656.97 4432.38,5661.97 4453.26,5661.97 4488.85,5697.56 4566.66,5697.56 4567.05,5697.95 4581.31,5697.95 4595.33,5711.97 4638.31,5711.97 4681.78,5668.5 4681.78,5519.34 4694.78,5506.34 4720.68,5506.34 4762.52,5548.19 4840.92,5548.19 4850.92,5558.19 4932.2,5558.19 4938.64,5551.75 4938.64,5474.59 U8.8@4930.39,5466.34 ; U8.8@5271.11,6330.08 5262.86,6321.84 5262.86,6244.67 5269.29,6238.24 5350.58,6238.24 5360.58,6248.24 5438.97,6248.24 5480.82,6290.08 5506.72,6290.08 5519.71,6277.09 5519.71,6127.92 5563.19,6084.45 5606.17,6084.45 5620.18,6098.47 5634.44,6098.47 5634.83,6098.86 5712.64,6098.86 5748.24,6134.45 5769.12,6134.45 Q1.1@5774.12,6139.45 5804.75,6170.08 5851.72,6170.08 5858.79,6177.15 R54.2@5858.76,6225.08 ; U8.8@5271.77,4361.58 5263.53,4353.33 5263.53,4276.17 5269.96,4269.73 5351.25,4269.73 5361.25,4279.73 5439.64,4279.73 5481.49,4321.58 5507.38,4321.58 5520.38,4308.58 5520.38,4159.42 5563.85,4115.95 5606.83,4115.95 5620.85,4129.96 5635.11,4129.96 5635.5,4130.36 5713.31,4130.36 5748.9,4165.95 5769.78,4165.95 Q1.1@5774.78,4170.95 5805.41,4201.58 5852.38,4201.58 5859.45,4208.65 R54.2@5859.45,4256.55 ; U8.8@5271.77,5345.83 5263.53,5337.58 5263.53,5260.42 5269.96,5253.98 5351.25,5253.98 5361.25,5263.98 5439.64,5263.98 5481.49,5305.83 5507.38,5305.83 5520.38,5292.83 5520.38,5143.67 5563.85,5100.2 5606.83,5100.2 5620.85,5114.22 5635.11,5114.22 5635.5,5114.61 5713.31,5114.61 5748.9,5150.2 5769.78,5150.2 Q1.1@5774.78,5155.2 5805.41,5185.83 5852.38,5185.83 5859.45,5192.9 R54.2@5859.45,5240.8 ; U8.8@5272.44,3377.33 5264.2,3369.08 5264.2,3291.91 5270.63,3285.48 5351.91,3285.48 5361.91,3295.48 5440.31,3295.48 5482.15,3337.33 5508.05,3337.33 5521.05,3324.33 5521.05,3175.17 5564.52,3131.7 5607.5,3131.7 5621.52,3145.71 5635.78,3145.71 5636.17,3146.1 5713.98,3146.1 5749.57,3181.7 5770.45,3181.7 Q1.1@5775.45,3186.7 5806.08,3217.33 5853.05,3217.33 5860.12,3224.4 R54.2@5860.09,3272.33 ; R54.2@5858.76,6225.08 5956.72,6225.08 6030.34,6151.46 6778.09,6151.46 6846.57,6219.94 6846.57,6263.16 6879.01,6295.59 6898.48,6295.59 USB1.A4B9@6898.74,6295.85 ; R54.2@5859.42,4256.58 5957.38,4256.58 6031.01,4182.96 6778.76,4182.96 6847.24,4251.44 6847.24,4294.66 6879.67,4327.09 6899.15,4327.09 USB1.A4B9@6899.41,4327.34 ; R54.2@5859.42,5240.83 5957.38,5240.83 6031.01,5167.21 6778.76,5167.21 6847.24,5235.69 6847.24,5278.91 6879.67,5311.34 6899.15,5311.34 USB1.A4B9@6899.41,5311.59 ; R54.2@5860.09,3272.33 5958.05,3272.33 6031.67,3198.7 6779.43,3198.7 6847.91,3267.18 6847.91,3310.4 6880.34,3342.83 6899.82,3342.83 USB1.A4B9@6900.07,3343.09 ; D6.2@6844.41,6550.08 6844.41,6492.9 6852.48,6484.83 USB1.B4A9@6905.63,6484.83 ; D6.2@6845.08,4581.58 6845.08,4524.39 6853.15,4516.32 USB1.B4A9@6906.3,4516.32 ; D6.2@6845.08,5565.83 6845.08,5508.64 6853.15,5500.57 USB1.B4A9@6906.3,5500.57 ; D6.2@6845.75,3597.33 6845.75,3540.14 6853.81,3532.07 USB1.B4A9@6906.96,3532.07
RX: U6.30 U9.6 | length 1527.4
  Top Layer w10: U9.6@3651.89,6364.53 3718.64,6364.53 3769.82,6313.35 U6.30@3821.61,6313.35 ; U9.6@3652.55,4396.02 3719.31,4396.02 3770.49,4344.84 U6.30@3822.28,4344.84 ; U9.6@3652.55,5380.28 3719.31,5380.28 3770.49,5329.09 U6.30@3822.28,5329.09 ; U9.6@3653.22,3411.77 3719.98,3411.77 3771.16,3360.59 U6.30@3822.95,3360.59 ; U6.30@6379.22,6467.33 6431,6467.33 6482.18,6416.15 U9.6@6548.94,6416.15 ; U6.30@6379.88,4498.82 6431.67,4498.82 6482.85,4447.64 U9.6@6549.61,4447.64 ; U6.30@6379.88,5483.07 6431.67,5483.07 6482.85,5431.89 U9.6@6549.61,5431.89 ; U6.30@6380.55,3514.57 6432.34,3514.57 6483.52,3463.39 U9.6@6550.28,3463.39
TX: U6.31 U9.7 | length 1788.2
  Bottom Layer w10: v1(3653.85,6416.5) 3788.5,6281.85 v1(3821.61,6281.85) ; v1(3654.52,4447.99) 3789.17,4313.35 v1(3822.28,4313.35) ; v1(3654.52,5432.24) 3789.17,5297.6 v1(3822.28,5297.6) ; v1(3655.19,3463.74) 3789.84,3329.09 v1(3822.95,3329.09) ; v1(6379.22,6498.82) 6412.33,6498.82 v1(6546.97,6364.18) ; v1(6379.88,4530.32) 6412.99,4530.32 v1(6547.64,4395.67) ; v1(6379.88,5514.57) 6412.99,5514.57 v1(6547.64,5379.92) ; v1(6380.55,3546.07) 6413.66,3546.07 v1(6548.31,3411.42)
XTAL1: U6.7 X1.1 | length 5029
  Top Layer w10: X1.1@3597.58,6082.28 3597.58,6056.68 3610.37,6043.88 4033.38,6043.88 4049.11,6059.61 4049.11,6130.59 4061.2,6142.68 4061.2,6177.27 v1(4072.48,6188.55) ; X1.1@3598.24,4113.78 3598.24,4088.17 3611.04,4075.38 4034.05,4075.38 4049.78,4091.1 4049.78,4162.09 4061.87,4174.17 4061.87,4208.76 v1(4073.15,4220.05) ; X1.1@3598.24,5098.03 3598.24,5072.43 3614.98,5055.69 4030.12,5055.69 4049.78,5075.35 4049.78,5146.34 4061.87,5158.43 4061.87,5193.02 v1(4073.15,5204.3) ; X1.1@3598.91,3129.52 3598.91,3103.92 3615.65,3087.19 4030.78,3087.19 4050.45,3106.85 4050.45,3177.83 4062.53,3189.92 4062.53,3224.51 v1(4073.82,3235.79) ; v1(6128.34,6592.12) 6139.63,6603.41 6139.63,6638 6151.72,6650.08 6151.72,6721.07 6167.44,6736.79 6590.45,6736.79 6603.25,6724 X1.1@6603.25,6698.39 ; v1(6129.01,4623.62) 6140.3,4634.9 6140.3,4669.49 6152.38,4681.58 6152.38,4752.56 6168.11,4768.29 6591.12,4768.29 6603.92,4755.49 X1.1@6603.92,4729.89 ; v1(6129.01,5607.87) 6140.3,5619.15 6140.3,5653.74 6152.38,5665.83 6152.38,5736.81 6172.05,5756.48 6587.18,5756.48 6603.92,5739.74 X1.1@6603.92,5714.14 ; v1(6129.68,3639.36) 6140.97,3650.65 6140.97,3685.24 6153.05,3697.33 6153.05,3768.31 6167.07,3782.33 6593.5,3782.33 6604.59,3771.24 X1.1@6604.59,3745.64
pads on no net: LED1.1 LED1.2 LED1.3 LED1.4 LED1.5 LED1.6 LED1.7 LED1.8 LED1.9 LED1.10 LED1.11 LED1.12 LED1.13 LED1.14 U6.8 U6.20 U6.29 U8.6 U8.7 U8.9 U9.4 U9.8 U12.1 U12.3 U12.4 U13.5@4337.1,6198.41 U13.5@4337.77,4229.9 U13.5@4337.77,5214.16 U13.5@4338.44,3245.65 U13.5@4374.11,6089.63 U13.5@4374.78,4121.12 U13.5@4374.78,5105.38 U13.5@4375.45,3136.87 U13.5@4674.12,6089.63 U13.5@4674.79,4121.12 U13.5@4674.79,5105.37 U13.5@4675.45,3136.87 U13.5@4711.12,6198.41 U13.5@4711.79,4229.9 U13.5@4711.79,5214.16 U13.5@4712.45,3245.65 U13.5@5490.38,4613.76 U13.5@5490.38,5598.01 U13.5@5527.38,4722.54 U13.5@5527.38,5706.8 U13.5@5528.05,3738.29 U13.5@5827.38,4722.54 U13.5@5827.38,5706.79 U13.5@5828.05,3738.29 U13.5@5864.39,4613.76 U13.5@5864.39,5598.01 U13.5@5865.06,3629.51 U15.1 U15.2 U15.3 U15.4 U15.5 U15.6 U15.7 U15.8 U15.9 U15.10 U15.11 U15.12 U15.13 U15.14 USB1.0 USB1.A8 USB1.B8 X1.4

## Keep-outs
Board Outline Layer:
  region: 3136.51,5701.61 cw(c3089.27,5701.61) 3042.02,5701.61 cw(c3089.27,5701.61)
  region: 4947.53,5701.61 cw(c4900.29,5701.61) 4853.05,5701.61 cw(c4900.29,5701.61)
  region: 5349.12,5701.11 cw(c5301.87,5701.11) 5254.63,5701.11 cw(c5301.87,5701.11)
  region: 7160.14,5701.11 cw(c7112.9,5701.11) 7065.65,5701.11 cw(c7112.9,5701.11)
  region: 4987.01,5366.71 4987.01,5445.45 5223.23,5445.45 5223.23,5366.71
  region: 3136.51,4717.36 cw(c3089.27,4717.36) 3042.02,4717.36 cw(c3089.27,4717.36)
  region: 3448.26,5032.78 3625.43,5032.78 3625.43,4796.56 3310.47,4796.56 3310.47,5032.78
  region: 4522.97,5032.05 4680.45,5032.05 4680.45,4795.83 4365.49,4795.83 4365.49,5032.05
  region: 4947.53,4717.36 cw(c4900.29,4717.36) 4853.05,4717.36 cw(c4900.29,4717.36)
  region: 3971.89,5032.78 4152.99,5032.78 4152.99,4796.56 3838.03,4796.56 3838.03,5032.78
  region: 5349.12,4716.85 cw(c5301.87,4716.85) 5254.63,4716.85 cw(c5301.87,4716.85)
  region: 5679.92,5032.07 5837.4,5032.07 5837.4,4795.85 5522.44,4795.85 5522.44,5032.07
  region: 6207.48,5032.07 6364.96,5032.07 6364.96,4795.85 6050,4795.85 6050,5032.07
  region: 6734.94,5031.34 6892.42,5031.34 6892.42,4795.12 6577.46,4795.12 6577.46,5031.34
  region: 7160.14,4716.85 cw(c7112.9,4716.85) 7065.65,4716.85 cw(c7112.9,4716.85)
  region: 3136.51,5111.06 cw(c3089.27,5111.06) 3042.02,5111.06 cw(c3089.27,5111.06)
  region: 5376.77,4795.85 5219.29,4795.85 5219.29,4791.91 5219.19,4791.91 5219.19,4638.62 4982.97,4638.62 4982.97,4795.83 4826.12,4795.83 4825.59,4795.85 4825.59,5032.07 4983.07,5032.07 4983.07,5189.55 5219.29,5189.55 5219.29,5032.07 5376.77,5032.07
  region: 4947.53,5111.06 cw(c4900.29,5111.06) 4853.05,5111.06 cw(c4900.29,5111.06)
  region: 5349.12,5110.55 cw(c5301.87,5110.55) 5254.63,5110.55 cw(c5301.87,5110.55)
  region: 7160.14,5110.55 cw(c7112.9,5110.55) 7065.65,5110.55 cw(c7112.9,5110.55)
  region: 3136.51,4126.81 cw(c3089.27,4126.81) 3042.02,4126.81 cw(c3089.27,4126.81)
  region: 3539.48,3812.31 3311.14,3812.31 3311.14,4048.53 3626.1,4048.53 3626.1,3812.31
  region: 4523.64,4047.8 4681.12,4047.8 4681.12,3811.58 4366.16,3811.58 4366.16,4047.8
  region: 4947.53,4126.81 cw(c4900.29,4126.81) 4853.05,4126.81 cw(c4900.29,4126.81)
  region: 4063.11,3812.31 3838.7,3812.31 3838.7,4048.53 4153.66,4048.53 4153.66,3812.31
  region: 4987.01,4382.46 4987.01,4461.2 5223.23,4461.2 5223.23,4382.46
  region: 5349.12,4126.3 cw(c5301.87,4126.3) 5254.63,4126.3 cw(c5301.87,4126.3)
  region: 5653.03,4047.82 5838.07,4047.82 5838.07,3811.6 5523.11,3811.6 5523.11,4047.82
  region: 7160.14,4126.3 cw(c7112.9,4126.3) 7065.65,4126.3 cw(c7112.9,4126.3)
  region: 6208.15,4047.82 6365.63,4047.82 6365.63,3811.6 6050.67,3811.6 6050.67,4047.82
  region: 6735.61,4047.08 6893.09,4047.08 6893.09,3810.86 6578.13,3810.86 6578.13,4047.08
  region: 3137.18,3142.56 cw(c3089.94,3142.56) 3042.69,3142.56 cw(c3089.94,3142.56)
  region: 4948.2,3142.56 cw(c4900.96,3142.56) 4853.71,3142.56 cw(c4900.96,3142.56)
  region: 4987.68,3398.21 4987.68,3476.95 5223.9,3476.95 5223.9,3398.21
  region: 5349.78,3142.05 cw(c5302.54,3142.05) 5255.3,3142.05 cw(c5302.54,3142.05)
  region: 7160.81,3142.05 cw(c7113.56,3142.05) 7066.32,3142.05 cw(c7113.56,3142.05)
  region: 3137.18,3733.11 cw(c3089.94,3733.11) 3042.69,3733.11 cw(c3089.94,3733.11)
  region: 5219.29,4205.3 5219.29,4047.82 5377.44,4047.82 5377.44,3811.6 5219.96,3811.6 5219.96,3807.66 5219.86,3807.66 5219.86,3654.37 4983.64,3654.37 4983.64,3811.58 4826.79,3811.58 4826.26,3811.6 4826.26,4047.82 4983.07,4047.82 4983.07,4205.3
  region: 4948.2,3733.11 cw(c4900.96,3733.11) 4853.71,3733.11 cw(c4900.96,3733.11)
  region: 5349.78,3732.6 cw(c5302.54,3732.6) 5255.3,3732.6 cw(c5302.54,3732.6)
  region: 7160.81,3732.6 cw(c7113.56,3732.6) 7066.32,3732.6 cw(c7113.56,3732.6)
  region: 3135.84,6095.32 cw(c3088.6,6095.32) 3041.35,6095.32 cw(c3088.6,6095.32)
  region: 3135.84,6685.87 cw(c3088.6,6685.87) 3041.35,6685.87 cw(c3088.6,6685.87)
  region: 3538.82,5780.82 3310.47,5780.82 3310.47,6017.04 3625.43,6017.04 3625.43,5780.82
  region: 4062.44,5780.82 3838.03,5780.82 3838.03,6017.04 4152.99,6017.04 4152.99,5780.82
  region: 4946.87,6095.32 cw(c4899.62,6095.32) 4852.38,6095.32 cw(c4899.62,6095.32)
  region: 4946.87,6685.87 cw(c4899.62,6685.87) 4852.38,6685.87 cw(c4899.62,6685.87)
  region: 4986.34,6350.97 4986.34,6429.71 5222.56,6429.71 5222.56,6350.97
  region: 5348.45,6685.36 cw(c5301.2,6685.36) 5253.96,6685.36 cw(c5301.2,6685.36)
  region: 5348.45,6094.81 cw(c5301.2,6094.81) 5253.96,6094.81 cw(c5301.2,6094.81)
  region: 5652.36,6016.32 5837.4,6016.32 5837.4,5780.1 5522.44,5780.1 5522.44,6016.32
  region: 6207.48,6016.32 6364.96,6016.32 6364.96,5780.1 6050,5780.1 6050,6016.32
  region: 6734.94,6015.59 6892.42,6015.59 6892.42,5779.37 6577.46,5779.37 6577.46,6015.59
  region: 7159.47,6685.36 cw(c7112.23,6685.36) 7064.98,6685.36 cw(c7112.23,6685.36)
  region: 7159.47,6094.81 cw(c7112.23,6094.81) 7064.98,6094.81 cw(c7112.23,6094.81)
  region: 5218.52,6760.42 5218.52,6607.13 4982.3,6607.13 4982.3,6764.34 4983.33,6764.35 5218.62,6764.35 5218.62,6760.42
  region: 7195.57,6015.59 7195.57,5779.37 7038.09,5779.37 7038.09,6015.59
  region: 4680.45,6016.3 4680.45,5780.08 4365.49,5780.08 4365.49,6016.3
  region: 5219.19,5776.16 5219.19,5622.87 4982.97,5622.87 4982.97,5780.08 4826.12,5780.08 4825.59,5780.1 4825.59,6016.32 4982.4,6016.32 4982.4,6173.8 5218.62,6173.8 5218.62,6016.32 5376.77,6016.32 5376.77,5780.1 5219.29,5780.1 5219.29,5776.16
  region: 3165.47,4048.53 3165.47,3812.31 3007.99,3812.31 3007.99,4048.53
  region: 5219.96,3221.04 5219.96,3063.56 4983.74,3063.56 4983.74,3221.04
  region: 7038.76,3810.86 7038.76,4047.08 7196.24,4047.08 7196.24,3810.86
  region: 3006.59,4796.1 3006.59,5032.32 3164.8,5032.78 3164.8,4795.89 3164.59,4796.1
  region: 7195.57,5031.34 7195.57,4795.12 7038.09,4795.12 7038.09,5031.34
  region: 3003.38,5780.82 3003.38,6017.04 3164.8,6017.04 3164.8,5780.82
  lines w1: 3003.38,5780.82 3003.38,6017.04 3164.8,6017.04 3164.8,5780.82 3003.38,5780.82 ; 3006.59,4796.1 3006.59,5032.32 3164.8,5032.78 3164.8,4795.89 3164.59,4796.1 3006.59,4796.1 ; 3007.99,3812.31 3165.47,3812.31 3165.47,4048.53 3007.99,4048.53 3007.99,3812.31 ; 3041.35,6095.32 ccw(c3088.6,6095.32) 3135.84,6095.32 ccw(c3088.6,6095.32) 3041.35,6095.32 ; 3041.35,6685.87 ccw(c3088.6,6685.87) 3135.84,6685.87 ccw(c3088.6,6685.87) 3041.35,6685.87 ; 3042.02,4126.81 ccw(c3089.27,4126.81) 3136.51,4126.81 ccw(c3089.27,4126.81) 3042.02,4126.81 ; 3042.02,4717.36 ccw(c3089.27,4717.36) 3136.51,4717.36 ccw(c3089.27,4717.36) 3042.02,4717.36 ; 3042.02,5111.06 ccw(c3089.27,5111.06) 3136.51,5111.06 ccw(c3089.27,5111.06) 3042.02,5111.06 ; 3042.02,5701.61 ccw(c3089.27,5701.61) 3136.51,5701.61 ccw(c3089.27,5701.61) 3042.02,5701.61 ; 3042.69,3142.56 ccw(c3089.94,3142.56) 3137.18,3142.56 ccw(c3089.94,3142.56) 3042.69,3142.56 ; 3042.69,3733.11 ccw(c3089.94,3733.11) 3137.18,3733.11 ccw(c3089.94,3733.11) 3042.69,3733.11 ; 3310.47,4796.56 3625.43,4796.56 3625.43,5032.78 3448.26,5032.78 3310.47,5032.78 3310.47,4796.56 ; 3310.47,5780.82 3538.82,5780.82 3625.43,5780.82 3625.43,6017.04 3310.47,6017.04 3310.47,5780.82 ; 3311.14,3812.31 3539.48,3812.31 3626.1,3812.31 3626.1,4048.53 3311.14,4048.53 3311.14,3812.31 ; 3838.03,4796.56 4152.99,4796.56 4152.99,5032.78 3971.89,5032.78 3838.03,5032.78 3838.03,4796.56 ; 3838.03,5780.82 4062.44,5780.82 4152.99,5780.82 4152.99,6017.04 3838.03,6017.04 3838.03,5780.82 ; 3838.7,3812.31 4063.11,3812.31 4153.66,3812.31 4153.66,4048.53 3838.7,4048.53 3838.7,3812.31 ; 4365.49,4795.83 4680.45,4795.83 4680.45,5032.05 4522.97,5032.05 4365.49,5032.05 4365.49,4795.83 ; 4365.49,5780.08 4680.45,5780.08 4680.45,6016.3 4365.49,6016.3 4365.49,5780.08 ; 4366.16,3811.58 4681.12,3811.58 4681.12,4047.8 4523.64,4047.8 4366.16,4047.8 4366.16,3811.58 ; 4825.59,4795.85 4826.12,4795.83 4982.97,4795.83 4982.97,4638.62 5219.19,4638.62 5219.19,4791.91 5219.29,4791.91 5219.29,4795.85 5376.77,4795.85 5376.77,5032.07 5219.29,5032.07 5219.29,5189.55 4983.07,5189.55 4983.07,5032.07 4825.59,5032.07 4825.59,4795.85 ; 4825.59,5780.1 4826.12,5780.08 4982.97,5780.08 4982.97,5622.87 5219.19,5622.87 5219.19,5776.16 5219.29,5776.16 5219.29,5780.1 5376.77,5780.1 5376.77,6016.32 5218.62,6016.32 5218.62,6173.8 4982.4,6173.8 4982.4,6016.32 4825.59,6016.32 4825.59,5780.1 ; 4826.26,3811.6 4826.79,3811.58 4983.64,3811.58 4983.64,3654.37 5219.86,3654.37 5219.86,3807.66 5219.96,3807.66 5219.96,3811.6 5377.44,3811.6 5377.44,4047.82 5219.29,4047.82 5219.29,4205.3 4983.07,4205.3 4983.07,4047.82 4826.26,4047.82 4826.26,3811.6 ; 4852.38,6095.32 ccw(c4899.62,6095.32) 4946.87,6095.32 ccw(c4899.62,6095.32) 4852.38,6095.32 ; 4852.38,6685.87 ccw(c4899.62,6685.87) 4946.87,6685.87 ccw(c4899.62,6685.87) 4852.38,6685.87 ; 4853.05,4126.81 ccw(c4900.29,4126.81) 4947.53,4126.81 ccw(c4900.29,4126.81) 4853.05,4126.81 ; 4853.05,4717.36 ccw(c4900.29,4717.36) 4947.53,4717.36 ccw(c4900.29,4717.36) 4853.05,4717.36 ; 4853.05,5111.06 ccw(c4900.29,5111.06) 4947.53,5111.06 ccw(c4900.29,5111.06) 4853.05,5111.06 ; 4853.05,5701.61 ccw(c4900.29,5701.61) 4947.53,5701.61 ccw(c4900.29,5701.61) 4853.05,5701.61 ; 4853.71,3142.56 ccw(c4900.96,3142.56) 4948.2,3142.56 ccw(c4900.96,3142.56) 4853.71,3142.56 ; 4853.71,3733.11 ccw(c4900.96,3733.11) 4948.2,3733.11 ccw(c4900.96,3733.11) 4853.71,3733.11 ; 4982.3,6607.13 5218.52,6607.13 5218.52,6760.42 5218.62,6760.42 5218.62,6764.35 4983.33,6764.35 4982.3,6764.34 4982.3,6607.13 ; 4983.74,3063.56 5219.96,3063.56 5219.96,3221.04 4983.74,3221.04 4983.74,3063.56 ; 4986.34,6350.97 4986.34,6429.71 5222.56,6429.71 5222.56,6350.97 4986.34,6350.97 ; 4987.01,4382.46 4987.01,4461.2 5223.23,4461.2 5223.23,4382.46 4987.01,4382.46 ; 4987.01,5366.71 4987.01,5445.45 5223.23,5445.45 5223.23,5366.71 4987.01,5366.71 ; 4987.68,3398.21 4987.68,3476.95 5223.9,3476.95 5223.9,3398.21 4987.68,3398.21 ; 5253.96,6094.81 ccw(c5301.2,6094.81) 5348.45,6094.81 ccw(c5301.2,6094.81) 5253.96,6094.81 ; 5253.96,6685.36 ccw(c5301.2,6685.36) 5348.45,6685.36 ccw(c5301.2,6685.36) 5253.96,6685.36 ; 5254.63,4126.3 ccw(c5301.87,4126.3) 5349.12,4126.3 ccw(c5301.87,4126.3) 5254.63,4126.3 ; 5254.63,4716.85 ccw(c5301.87,4716.85) 5349.12,4716.85 ccw(c5301.87,4716.85) 5254.63,4716.85 ; 5254.63,5110.55 ccw(c5301.87,5110.55) 5349.12,5110.55 ccw(c5301.87,5110.55) 5254.63,5110.55 ; 5254.63,5701.11 ccw(c5301.87,5701.11) 5349.12,5701.11 ccw(c5301.87,5701.11) 5254.63,5701.11 ; 5255.3,3142.05 ccw(c5302.54,3142.05) 5349.78,3142.05 ccw(c5302.54,3142.05) 5255.3,3142.05 ; 5255.3,3732.6 ccw(c5302.54,3732.6) 5349.78,3732.6 ccw(c5302.54,3732.6) 5255.3,3732.6 ; 5522.44,4795.85 5837.4,4795.85 5837.4,5032.07 5679.92,5032.07 5522.44,5032.07 5522.44,4795.85 ; 5522.44,5780.1 5837.4,5780.1 5837.4,6016.32 5652.36,6016.32 5522.44,6016.32 5522.44,5780.1 ; 5523.11,3811.6 5838.07,3811.6 5838.07,4047.82 5653.03,4047.82 5523.11,4047.82 5523.11,3811.6 ; 6050,4795.85 6364.96,4795.85 6364.96,5032.07 6207.48,5032.07 6050,5032.07 6050,4795.85 ; 6050,5780.1 6364.96,5780.1 6364.96,6016.32 6207.48,6016.32 6050,6016.32 6050,5780.1 ; 6050.67,3811.6 6365.63,3811.6 6365.63,4047.82 6208.15,4047.82 6050.67,4047.82 6050.67,3811.6 ; 6577.46,4795.12 6892.42,4795.12 6892.42,5031.34 6734.94,5031.34 6577.46,5031.34 6577.46,4795.12 ; 6577.46,5779.37 6892.42,5779.37 6892.42,6015.59 6734.94,6015.59 6577.46,6015.59 6577.46,5779.37 ; 6578.13,3810.86 6893.09,3810.86 6893.09,4047.08 6735.61,4047.08 6578.13,4047.08 6578.13,3810.86 ; 7038.09,4795.12 7195.57,4795.12 7195.57,5031.34 7038.09,5031.34 7038.09,4795.12 ; 7038.09,5779.37 7195.57,5779.37 7195.57,6015.59 7038.09,6015.59 7038.09,5779.37 ; 7038.76,3810.86 7038.76,4047.08 7196.24,4047.08 7196.24,3810.86 7038.76,3810.86 ; 7064.98,6094.81 ccw(c7112.23,6094.81) 7159.47,6094.81 ccw(c7112.23,6094.81) 7064.98,6094.81 ; 7064.98,6685.36 ccw(c7112.23,6685.36) 7159.47,6685.36 ccw(c7112.23,6685.36) 7064.98,6685.36 ; 7065.65,4126.3 ccw(c7112.9,4126.3) 7160.14,4126.3 ccw(c7112.9,4126.3) 7065.65,4126.3 ; 7065.65,4716.85 ccw(c7112.9,4716.85) 7160.14,4716.85 ccw(c7112.9,4716.85) 7065.65,4716.85 ; 7065.65,5110.55 ccw(c7112.9,5110.55) 7160.14,5110.55 ccw(c7112.9,5110.55) 7065.65,5110.55 ; 7065.65,5701.11 ccw(c7112.9,5701.11) 7160.14,5701.11 ccw(c7112.9,5701.11) 7065.65,5701.11 ; 7066.32,3142.05 ccw(c7113.56,3142.05) 7160.81,3142.05 ccw(c7113.56,3142.05) 7066.32,3142.05 ; 7066.32,3732.6 ccw(c7113.56,3732.6) 7160.81,3732.6 ccw(c7113.56,3732.6) 7066.32,3732.6
  lines w10: 3005.43,6205.96 3005.73,5776.17 3006.58,5776.17 3006.1,5591.71 3266.1,5591.71 3266.1,5221.71 3006.1,5221.71 3006.59,5032.32 3006.59,4796.1 3006.1,4607.46 3266.1,4607.46 3266.1,4237.46 3006.1,4237.46 3006.59,4048.07 3007.99,4048.07 3007.99,3811.85 3007.26,3811.85 3006.77,3623.21 3266.77,3623.21 3266.77,3253.21 3006.77,3253.21 3007.26,3063.82 5219.19,3063.82 7196.24,3063.31 7196.73,3251.95 6936.73,3251.95 6936.73,3621.95 7196.73,3621.95 7196.24,3811.34 7195.57,3811.34 7195.57,4047.56 7196.06,4236.2 6936.06,4236.2 6936.06,4606.2 7196.06,4606.2 7195.57,4795.59 7195.57,5031.81 7196.06,5220.46 6936.06,5220.46 6936.06,5590.46 7196.06,5590.46 7195.57,5779.85 7195.45,5779.85 7195.39,6204.71 6935.39,6204.71 6935.39,6574.71 7195.39,6574.71 7195.18,6764.09 3005.65,6764.6 3005.43,6575.96 3265.43,6575.96 3265.43,6205.96 3005.43,6205.96

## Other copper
Top Layer:
  region net $1N14266: 3724.78,5706.34 cw(c3694.78,5706.34) 3664.78,5706.34 cw(c3694.78,5706.34)
  region net $1N14266: 3824.68,5706.08 cw(c3794.68,5706.08) 3764.68,5706.08 cw(c3794.68,5706.08)
  region net $1N14266: 3924.68,5706.08 cw(c3894.68,5706.08) 3864.68,5706.08 cw(c3894.68,5706.08)
  region net $1N14266: 4024.68,5706.08 cw(c3994.68,5706.08) 3964.68,5706.08 cw(c3994.68,5706.08)
  region net $1N14266: 4124.68,5706.08 cw(c4094.68,5706.08) 4064.68,5706.08 cw(c4094.68,5706.08)
  region net $1N14266: 3724.68,5106.08 cw(c3694.68,5106.08) 3664.68,5106.08 cw(c3694.68,5106.08)
  region net $1N14266: 3824.68,5106.08 cw(c3794.68,5106.08) 3764.68,5106.08 cw(c3794.68,5106.08)
  region net $1N14266: 3924.68,5106.08 cw(c3894.68,5106.08) 3864.68,5106.08 cw(c3894.68,5106.08)
  region net $1N14266: 4024.68,5106.08 cw(c3994.68,5106.08) 3964.68,5106.08 cw(c3994.68,5106.08)
  region net $1N14266: 4124.68,5106.08 cw(c4094.68,5106.08) 4064.68,5106.08 cw(c4094.68,5106.08)
  region net $1N14266: 4224.78,5106.34 cw(c4194.78,5106.34) 4164.78,5106.34 cw(c4194.78,5106.34)
  region net $1N14266: 4324.78,5106.34 cw(c4294.78,5106.34) 4264.78,5106.34 cw(c4294.78,5106.34)
  region net $1N14266: 4224.68,5706.08 cw(c4194.68,5706.08) 4164.68,5706.08 cw(c4194.68,5706.08)
  region net $1N14266: 4324.68,5706.08 cw(c4294.68,5706.08) 4264.68,5706.08 cw(c4294.68,5706.08)
  region net $1N14266: 3724.78,4722.09 cw(c3694.78,4722.09) 3664.78,4722.09 cw(c3694.78,4722.09)
  region net $1N14266: 3824.68,4721.83 cw(c3794.68,4721.83) 3764.68,4721.83 cw(c3794.68,4721.83)
  region net $1N14266: 3924.68,4721.83 cw(c3894.68,4721.83) 3864.68,4721.83 cw(c3894.68,4721.83)
  region net $1N14266: 4024.68,4721.83 cw(c3994.68,4721.83) 3964.68,4721.83 cw(c3994.68,4721.83)
  region net $1N14266: 4124.68,4721.83 cw(c4094.68,4721.83) 4064.68,4721.83 cw(c4094.68,4721.83)
  region net $1N14266: 4224.68,4721.83 cw(c4194.68,4721.83) 4164.68,4721.83 cw(c4194.68,4721.83)
  region net $1N14266: 4324.68,4721.83 cw(c4294.68,4721.83) 4264.68,4721.83 cw(c4294.68,4721.83)
  region net $1N14266: 3724.68,4121.83 cw(c3694.68,4121.83) 3664.68,4121.83 cw(c3694.68,4121.83)
  region net $1N14266: 3824.68,4121.83 cw(c3794.68,4121.83) 3764.68,4121.83 cw(c3794.68,4121.83)
  region net $1N14266: 3924.68,4121.83 cw(c3894.68,4121.83) 3864.68,4121.83 cw(c3894.68,4121.83)
  region net $1N14266: 4024.68,4121.83 cw(c3994.68,4121.83) 3964.68,4121.83 cw(c3994.68,4121.83)
  region net $1N14266: 4124.68,4121.83 cw(c4094.68,4121.83) 4064.68,4121.83 cw(c4094.68,4121.83)
  region net $1N14266: 4224.78,4122.09 cw(c4194.78,4122.09) 4164.78,4122.09 cw(c4194.78,4122.09)
  region net $1N14266: 4324.78,4122.09 cw(c4294.78,4122.09) 4264.78,4122.09 cw(c4294.78,4122.09)
Bottom Layer:
  region net $1N14266: 3724.78,5706.34 cw(c3694.78,5706.34) 3664.78,5706.34 cw(c3694.78,5706.34)
  region net $1N14266: 3824.68,5706.08 cw(c3794.68,5706.08) 3764.68,5706.08 cw(c3794.68,5706.08)
  region net $1N14266: 3924.68,5706.08 cw(c3894.68,5706.08) 3864.68,5706.08 cw(c3894.68,5706.08)
  region net $1N14266: 4024.68,5706.08 cw(c3994.68,5706.08) 3964.68,5706.08 cw(c3994.68,5706.08)
  region net $1N14266: 4124.68,5706.08 cw(c4094.68,5706.08) 4064.68,5706.08 cw(c4094.68,5706.08)
  region net $1N14266: 3724.68,5106.08 cw(c3694.68,5106.08) 3664.68,5106.08 cw(c3694.68,5106.08)
  region net $1N14266: 3824.68,5106.08 cw(c3794.68,5106.08) 3764.68,5106.08 cw(c3794.68,5106.08)
  region net $1N14266: 3924.68,5106.08 cw(c3894.68,5106.08) 3864.68,5106.08 cw(c3894.68,5106.08)
  region net $1N14266: 4024.68,5106.08 cw(c3994.68,5106.08) 3964.68,5106.08 cw(c3994.68,5106.08)
  region net $1N14266: 4124.68,5106.08 cw(c4094.68,5106.08) 4064.68,5106.08 cw(c4094.68,5106.08)
  region net $1N14266: 4224.78,5106.34 cw(c4194.78,5106.34) 4164.78,5106.34 cw(c4194.78,5106.34)
  region net $1N14266: 4324.78,5106.34 cw(c4294.78,5106.34) 4264.78,5106.34 cw(c4294.78,5106.34)
  region net $1N14266: 4224.68,5706.08 cw(c4194.68,5706.08) 4164.68,5706.08 cw(c4194.68,5706.08)
  region net $1N14266: 4324.68,5706.08 cw(c4294.68,5706.08) 4264.68,5706.08 cw(c4294.68,5706.08)
  region net $1N14266: 3724.78,4722.09 cw(c3694.78,4722.09) 3664.78,4722.09 cw(c3694.78,4722.09)
  region net $1N14266: 3824.68,4721.83 cw(c3794.68,4721.83) 3764.68,4721.83 cw(c3794.68,4721.83)
  region net $1N14266: 3924.68,4721.83 cw(c3894.68,4721.83) 3864.68,4721.83 cw(c3894.68,4721.83)
  region net $1N14266: 4024.68,4721.83 cw(c3994.68,4721.83) 3964.68,4721.83 cw(c3994.68,4721.83)
  region net $1N14266: 4124.68,4721.83 cw(c4094.68,4721.83) 4064.68,4721.83 cw(c4094.68,4721.83)
  region net $1N14266: 4224.68,4721.83 cw(c4194.68,4721.83) 4164.68,4721.83 cw(c4194.68,4721.83)
  region net $1N14266: 4324.68,4721.83 cw(c4294.68,4721.83) 4264.68,4721.83 cw(c4294.68,4721.83)
  region net $1N14266: 3724.68,4121.83 cw(c3694.68,4121.83) 3664.68,4121.83 cw(c3694.68,4121.83)
  region net $1N14266: 3824.68,4121.83 cw(c3794.68,4121.83) 3764.68,4121.83 cw(c3794.68,4121.83)
  region net $1N14266: 3924.68,4121.83 cw(c3894.68,4121.83) 3864.68,4121.83 cw(c3894.68,4121.83)
  region net $1N14266: 4024.68,4121.83 cw(c3994.68,4121.83) 3964.68,4121.83 cw(c3994.68,4121.83)
  region net $1N14266: 4124.68,4121.83 cw(c4094.68,4121.83) 4064.68,4121.83 cw(c4094.68,4121.83)
  region net $1N14266: 4224.78,4122.09 cw(c4194.78,4122.09) 4164.78,4122.09 cw(c4194.78,4122.09)
  region net $1N14266: 4324.78,4122.09 cw(c4294.78,4122.09) 4264.78,4122.09 cw(c4294.78,4122.09)
  text "B+" at 5661.72,6740.08 h78.74 r90
  text "B-" at 4534.11,6645.59 h78.74 r270
  text "B-" at 5666.72,6135.08 h78.74 r90
  text "B+" at 4539.11,6040.59 h78.74 r270
  text "B+" at 5662.38,5755.83 h78.74 r90
  text "B-" at 4534.78,5661.34 h78.74 r270
  text "B-" at 5667.38,5150.83 h78.74 r90
  text "B+" at 4539.78,5056.34 h78.74 r270
  text "B+" at 5662.38,4771.58 h78.74 r90
  text "B-" at 4534.78,4677.09 h78.74 r270
  text "B-" at 5667.38,4166.58 h78.74 r90
  text "B+" at 4539.78,4072.09 h78.74 r270
  text "B+" at 5663.05,3787.33 h78.74 r90
  text "B-" at 4535.45,3692.83 h78.74 r270
  text "B-" at 5668.05,3182.33 h78.74 r90
  text "B+" at 4540.45,3087.83 h78.74 r270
